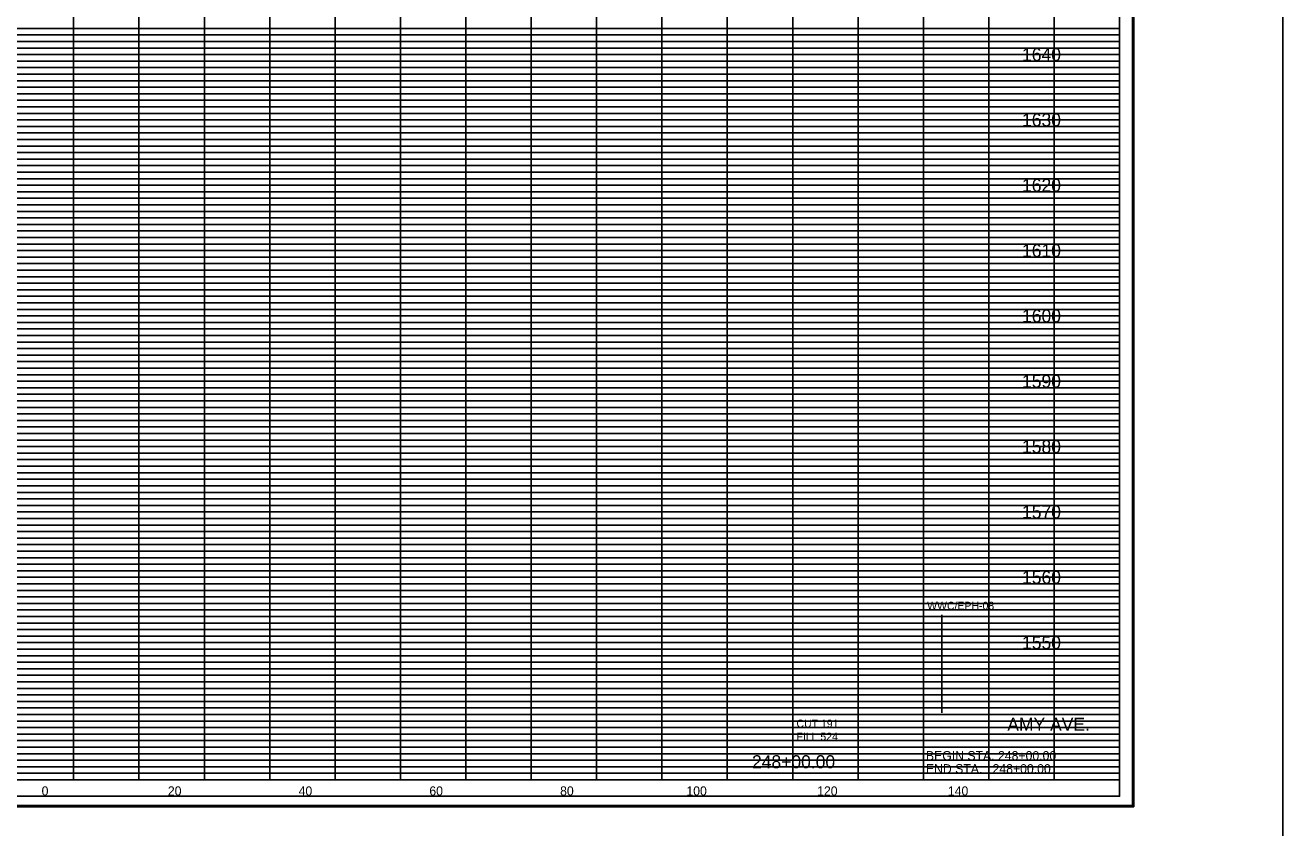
# Model space of a CAD drawing. Extents: x 955 to 1375, y 1248 to 3657.
# Drawn here: x 1152.6 to 1345, y 2612.7 to 2735.5 of the extents above; entities that cross this region are included whole.
import ezdxf

# ---------------------------------------------------------------- set-up
doc = ezdxf.new("R2010")
doc.units = 0
for name, color, linetype in [('DESIGN - SHEET - Corner Text', 7, 'Continuous'), ('DESIGN - SHEET - Light Grid', 7, 'Continuous'), ('DESIGN - SHEET - Linework', 7, 'Continuous'), ('DESIGN - SHEET - Plot Shape', 7, 'Continuous'), ('DESIGN - TYPICAL - Text', 7, 'Continuous'), ('DESIGN - UTILITIES - Cable (Overhead) with Text', 7, 'Continuous'), ('SURVEY - NON-TRANSPORTATION - Features', 7, 'Continuous'), ('SURVEY - NON-TRANSPORTATION - Features Text', 7, 'Continuous')]:
    doc.layers.add(name, color=color, linetype=linetype)

# ---------------------------------------------------------------- blocks, each defined once
blk = doc.blocks.new('XSTSHT')
at = {"layer": 'DESIGN - SHEET - Light Grid'}
for p, q in [((8, 11.5), (16, 11.5)), ((8, 11.4), (16, 11.4)), ((16, 11.5), (24, 11.5)), ((16, 11.4), (24, 11.4)), ((24, 11.5), (32, 11.5)), ((24, 11.4), (32, 11.4)), ((8, 11.3), (16, 11.3)), ((8, 11.2), (16, 11.2)), ((16, 11.3), (24, 11.3)), ((16, 11.2), (24, 11.2)), ((24, 11.3), (32, 11.3)), ((24, 11.2), (32, 11.2)), ((8, 11.1), (16, 11.1)), ((16, 11.1), (24, 11.1)), ((24, 11.1), (32, 11.1)), ((8, 10.9), (16, 10.9)), ((8, 10.8), (16, 10.8)), ((16, 10.9), (24, 10.9)), ((16, 10.8), (24, 10.8)), ((24, 10.9), (32, 10.9)), ((24, 10.8), (32, 10.8)), ((8, 10.7), (16, 10.7)), ((8, 10.6), (16, 10.6)), ((16, 10.7), (24, 10.7)), ((16, 10.6), (24, 10.6)), ((24, 10.7), (32, 10.7)), ((24, 10.6), (32, 10.6)), ((8, 10.5), (16, 10.5)), ((8, 10.4), (16, 10.4)), ((16, 10.5), (24, 10.5)), ((16, 10.4), (24, 10.4)), ((24, 10.5), (32, 10.5)), ((24, 10.4), (32, 10.4)), ((8, 10.3), (16, 10.3)), ((8, 10.2), (16, 10.2)), ((16, 10.3), (24, 10.3)), ((16, 10.2), (24, 10.2)), ((24, 10.3), (32, 10.3)), ((24, 10.2), (32, 10.2)), ((8, 10.1), (16, 10.1)), ((16, 10.1), (24, 10.1)), ((24, 10.1), (32, 10.1)), ((8, 9.9), (16, 9.9)), ((16, 9.9), (24, 9.9)), ((24, 9.9), (32, 9.9)), ((8, 9.8), (16, 9.8)), ((8, 9.7), (16, 9.7)), ((16, 9.8), (24, 9.8)), ((16, 9.7), (24, 9.7)), ((24, 9.8), (32, 9.8)), ((24, 9.7), (32, 9.7)), ((8, 9.6), (16, 9.6)), ((8, 9.5), (16, 9.5)), ((16, 9.6), (24, 9.6)), ((16, 9.5), (24, 9.5)), ((24, 9.6), (32, 9.6)), ((24, 9.5), (32, 9.5)), ((8, 9.4), (16, 9.4)), ((8, 9.3), (16, 9.3)), ((16, 9.4), (24, 9.4)), ((16, 9.3), (24, 9.3)), ((24, 9.4), (32, 9.4)), ((24, 9.3), (32, 9.3)), ((8, 9.2), (16, 9.2)), ((8, 9.1), (16, 9.1)), ((16, 9.2), (24, 9.2)), ((16, 9.1), (24, 9.1)), ((24, 9.2), (32, 9.2)), ((24, 9.1), (32, 9.1)), ((8, 8.9), (16, 8.9)), ((16, 8.9), (24, 8.9)), ((24, 8.9), (32, 8.9)), ((8, 8.8), (16, 8.8)), ((8, 8.7), (16, 8.7)), ((16, 8.8), (24, 8.8)), ((16, 8.7), (24, 8.7)), ((24, 8.8), (32, 8.8)), ((24, 8.7), (32, 8.7)), ((8, 8.6), (16, 8.6)), ((8, 8.5), (16, 8.5)), ((16, 8.6), (24, 8.6)), ((16, 8.5), (24, 8.5)), ((24, 8.6), (32, 8.6)), ((24, 8.5), (32, 8.5)), ((8, 8.4), (16, 8.4)), ((8, 8.3), (16, 8.3)), ((16, 8.4), (24, 8.4)), ((16, 8.3), (24, 8.3)), ((24, 8.4), (32, 8.4)), ((24, 8.3), (32, 8.3)), ((8, 8.2), (16, 8.2)), ((8, 8.1), (16, 8.1)), ((16, 8.2), (24, 8.2)), ((16, 8.1), (24, 8.1)), ((24, 8.2), (32, 8.2)), ((24, 8.1), (32, 8.1)), ((8, 7.9), (16, 7.9)), ((16, 7.9), (24, 7.9)), ((24, 7.9), (32, 7.9)), ((8, 7.8), (16, 7.8)), ((8, 7.7), (16, 7.7)), ((16, 7.8), (24, 7.8)), ((16, 7.7), (24, 7.7)), ((24, 7.8), (32, 7.8)), ((24, 7.7), (32, 7.7)), ((8, 7.6), (16, 7.6)), ((16, 7.6), (24, 7.6)), ((24, 7.6), (32, 7.6)), ((8, 7.5), (16, 7.5)), ((8, 7.4), (16, 7.4)), ((16, 7.5), (24, 7.5)), ((16, 7.4), (24, 7.4)), ((24, 7.5), (32, 7.5)), ((24, 7.4), (32, 7.4)), ((8, 7.3), (16, 7.3)), ((8, 7.2), (16, 7.2)), ((16, 7.3), (24, 7.3)), ((16, 7.2), (24, 7.2)), ((24, 7.3), (32, 7.3)), ((24, 7.2), (32, 7.2)), ((8, 7.1), (16, 7.1)), ((16, 7.1), (24, 7.1)), ((24, 7.1), (32, 7.1)), ((8, 6.9), (16, 6.9)), ((8, 6.8), (16, 6.8)), ((16, 6.9), (24, 6.9)), ((16, 6.8), (24, 6.8)), ((24, 6.9), (32, 6.9)), ((24, 6.8), (32, 6.8)), ((8, 6.7), (16, 6.7)), ((8, 6.6), (16, 6.6)), ((16, 6.7), (24, 6.7)), ((16, 6.6), (24, 6.6)), ((24, 6.7), (32, 6.7)), ((24, 6.6), (32, 6.6)), ((8, 6.5), (16, 6.5)), ((8, 6.4), (16, 6.4)), ((16, 6.5), (24, 6.5)), ((16, 6.4), (24, 6.4)), ((24, 6.5), (32, 6.5)), ((24, 6.4), (32, 6.4)), ((8, 6.3), (16, 6.3)), ((8, 6.2), (16, 6.2)), ((16, 6.3), (24, 6.3)), ((16, 6.2), (24, 6.2)), ((24, 6.3), (32, 6.3)), ((24, 6.2), (32, 6.2)), ((8, 6.1), (16, 6.1)), ((16, 6.1), (24, 6.1)), ((24, 6.1), (32, 6.1)), ((8, 5.9), (16, 5.9)), ((8, 5.8), (16, 5.8)), ((16, 5.9), (24, 5.9)), ((16, 5.8), (24, 5.8)), ((24, 5.9), (32, 5.9)), ((24, 5.8), (32, 5.8)), ((8, 5.7), (16, 5.7)), ((8, 5.6), (16, 5.6)), ((16, 5.7), (24, 5.7)), ((16, 5.6), (24, 5.6)), ((24, 5.7), (32, 5.7)), ((24, 5.6), (32, 5.6)), ((8, 5.5), (16, 5.5)), ((8, 5.4), (16, 5.4)), ((16, 5.5), (24, 5.5)), ((16, 5.4), (24, 5.4)), ((24, 5.5), (32, 5.5)), ((24, 5.4), (32, 5.4)), ((8, 5.3), (16, 5.3)), ((8, 5.2), (16, 5.2)), ((16, 5.3), (24, 5.3)), ((16, 5.2), (24, 5.2)), ((24, 5.3), (32, 5.3)), ((24, 5.2), (32, 5.2)), ((8, 5.1), (16, 5.1)), ((16, 5.1), (24, 5.1)), ((24, 5.1), (32, 5.1)), ((8, 4.9), (16, 4.9)), ((16, 4.9), (24, 4.9)), ((24, 4.9), (32, 4.9)), ((8, 4.8), (16, 4.8)), ((8, 4.7), (16, 4.7)), ((16, 4.8), (24, 4.8)), ((16, 4.7), (24, 4.7)), ((24, 4.8), (32, 4.8)), ((24, 4.7), (32, 4.7)), ((8, 4.6), (16, 4.6)), ((8, 4.5), (16, 4.5)), ((16, 4.6), (24, 4.6)), ((16, 4.5), (24, 4.5)), ((24, 4.6), (32, 4.6)), ((24, 4.5), (32, 4.5)), ((8, 4.4), (16, 4.4)), ((8, 4.3), (16, 4.3)), ((16, 4.4), (24, 4.4)), ((16, 4.3), (24, 4.3)), ((24, 4.4), (32, 4.4)), ((24, 4.3), (32, 4.3)), ((8, 4.2), (16, 4.2)), ((8, 4.1), (16, 4.1)), ((16, 4.2), (24, 4.2)), ((16, 4.1), (24, 4.1)), ((24, 4.2), (32, 4.2)), ((24, 4.1), (32, 4.1)), ((8, 3.9), (16, 3.9)), ((16, 3.9), (24, 3.9)), ((24, 3.9), (32, 3.9)), ((8, 3.8), (16, 3.8)), ((8, 3.7), (16, 3.7)), ((16, 3.8), (24, 3.8)), ((16, 3.7), (24, 3.7)), ((24, 3.8), (32, 3.8)), ((24, 3.7), (32, 3.7)), ((8, 3.6), (16, 3.6)), ((8, 3.5), (16, 3.5)), ((16, 3.6), (24, 3.6)), ((16, 3.5), (24, 3.5)), ((24, 3.6), (32, 3.6)), ((24, 3.5), (32, 3.5)), ((8, 3.4), (16, 3.4)), ((8, 3.3), (16, 3.3)), ((16, 3.4), (24, 3.4)), ((16, 3.3), (24, 3.3)), ((24, 3.4), (32, 3.4)), ((24, 3.3), (32, 3.3)), ((8, 3.2), (16, 3.2)), ((8, 3.1), (16, 3.1)), ((16, 3.2), (24, 3.2)), ((16, 3.1), (24, 3.1)), ((24, 3.2), (32, 3.2)), ((24, 3.1), (32, 3.1)), ((8, 2.9), (16, 2.9)), ((16, 2.9), (24, 2.9)), ((24, 2.9), (32, 2.9)), ((8, 2.8), (16, 2.8)), ((8, 2.7), (16, 2.7)), ((16, 2.8), (24, 2.8)), ((16, 2.7), (24, 2.7)), ((24, 2.8), (32, 2.8)), ((24, 2.7), (32, 2.7)), ((8, 2.6), (16, 2.6)), ((16, 2.6), (24, 2.6)), ((24, 2.6), (32, 2.6)), ((8, 2.5), (16, 2.5)), ((8, 2.4), (16, 2.4)), ((16, 2.5), (24, 2.5)), ((16, 2.4), (24, 2.4)), ((24, 2.5), (32, 2.5)), ((24, 2.4), (32, 2.4)), ((8, 2.3), (16, 2.3)), ((8, 2.2), (16, 2.2)), ((16, 2.3), (24, 2.3)), ((16, 2.2), (24, 2.2)), ((24, 2.3), (32, 2.3)), ((24, 2.2), (32, 2.2)), ((8, 2.1), (16, 2.1)), ((16, 2.1), (24, 2.1)), ((24, 2.1), (32, 2.1)), ((8, 1.9), (16, 1.9)), ((8, 1.8), (16, 1.8)), ((16, 1.9), (24, 1.9)), ((16, 1.8), (24, 1.8)), ((24, 1.9), (32, 1.9)), ((24, 1.8), (32, 1.8)), ((8, 1.7), (16, 1.7)), ((8, 1.6), (16, 1.6)), ((16, 1.7), (24, 1.7)), ((16, 1.6), (24, 1.6)), ((24, 1.7), (32, 1.7)), ((24, 1.6), (32, 1.6)), ((8, 1.5), (16, 1.5)), ((8, 1.4), (16, 1.4)), ((16, 1.5), (24, 1.5)), ((16, 1.4), (24, 1.4)), ((24, 1.5), (32, 1.5)), ((24, 1.4), (32, 1.4)), ((8, 1.3), (16, 1.3)), ((8, 1.2), (16, 1.2)), ((16, 1.3), (24, 1.3)), ((16, 1.2), (24, 1.2)), ((24, 1.3), (32, 1.3)), ((24, 1.2), (32, 1.2)), ((8, 1.1), (16, 1.1)), ((16, 1.1), (24, 1.1)), ((24, 1.1), (32, 1.1)), ((8, 0.9), (16, 0.9)), ((8, 0.8), (16, 0.8)), ((16, 0.9), (24, 0.9)), ((16, 0.8), (24, 0.8)), ((24, 0.9), (32, 0.9)), ((24, 0.8), (32, 0.8)), ((8, 0.7), (16, 0.7)), ((8, 0.6), (16, 0.6)), ((16, 0.7), (24, 0.7)), ((16, 0.6), (24, 0.6)), ((24, 0.7), (32, 0.7)), ((24, 0.6), (32, 0.6)), ((8, 0.5), (16, 0.5)), ((8, 0.4), (16, 0.4)), ((16, 0.5), (24, 0.5)), ((16, 0.4), (24, 0.4)), ((24, 0.5), (32, 0.5)), ((24, 0.4), (32, 0.4)), ((8, 0.3), (16, 0.3)), ((8, 0.2), (16, 0.2)), ((16, 0.3), (24, 0.3)), ((16, 0.2), (24, 0.2)), ((24, 0.3), (32, 0.3)), ((24, 0.2), (32, 0.2)), ((8, 0.1), (16, 0.1)), ((16, 0.1), (24, 0.1)), ((24, 0.1), (32, 0.1))]:
    blk.add_line(p, q, dxfattribs=at)
at = {"layer": 'DESIGN - SHEET - Linework'}
for p, q in [((32.217, 21.414), (32.217, -0.414)), ((16, 0), (16, 21)), ((17, 0), (17, 21)), ((18, 0), (18, 21)), ((19, 0), (19, 21)), ((20, 0), (20, 21)), ((21, 0), (21, 21)), ((22, 0), (22, 21)), ((23, 0), (23, 21)), ((24, 0), (24, 21)), ((25, 0), (25, 21)), ((26, 0), (26, 21)), ((27, 0), (27, 21)), ((28, 0), (28, 20)), ((29, 0), (29, 20)), ((30, 0), (30, 20)), ((31, 0), (31, 20)), ((0, 11), (32, 11)), ((0, 10), (32, 10)), ((0, 9), (32, 9)), ((0, 8), (32, 8)), ((0, 7), (32, 7)), ((0, 6), (32, 6)), ((0, 5), (32, 5)), ((0, 4), (32, 4)), ((0, 3), (32, 3)), ((0, 2), (32, 2)), ((0, 1), (32, 1)), ((-1.823, -0.414), (32.217, -0.414))]:
    blk.add_line(p, q, dxfattribs=at)
blk.add_lwpolyline([(0, 21), (0, 0), (32, 0), (32, 21), (0, 21)], dxfattribs=at)
at = {"layer": 'DESIGN - SHEET - Plot Shape'}
for points in [[(-1.803, 21.394), (32.197, 21.394), (32.197, -0.394), (-1.803, -0.394)], [(-0.85, 21), (32, 21), (32, -0.25), (-0.85, -0.25)]]:
    blk.add_lwpolyline(points, close=True, dxfattribs=at)

msp = doc.modelspace()

# ---------------------------------------------------------------- linework, layer by layer
at = {"layer": 'DESIGN - SHEET - Plot Shape'}
msp.add_lwpolyline([(991.5, 2617.5), (1320, 2617.5), (1320, 2830), (991.5, 2830)], close=True, dxfattribs=at)
at = {"layer": 'SURVEY - NON-TRANSPORTATION - Features'}
msp.add_line((1292.81, 2630.23), (1292.81, 2645.23), dxfattribs=at)
at = {"layer": 'SURVEY - NON-TRANSPORTATION - Features Text'}
msp.add_lwpolyline([(955.41, 1505.76), (1344.98, 1505.76), (1344.98, 3398.01), (955.41, 3398.01)], close=True, dxfattribs=at)

# ---------------------------------------------------------------- block references
at = {"layer": 'DESIGN - UTILITIES - Cable (Overhead) with Text', "xscale": 10, "yscale": 10}
msp.add_blockref('XSTSHT', (1000, 2620), dxfattribs=at)

# ---------------------------------------------------------------- texts
at = {"layer": 'DESIGN - SHEET - Corner Text'}
for s, height, p in [('AMY AVE.', 2, (1302.83, 2627.5)), ('BEGIN STA. 248+00.00', 1.4, (1290.38, 2623)), ('END STA.   248+00.00', 1.4, (1290.38, 2621))]:
    msp.add_text(s, height=height, dxfattribs=at).set_placement(p)
at = {"layer": 'DESIGN - TYPICAL - Text'}
for s, height, p in [('     1640     ', 2, (1301.37, 2730)), ('     1630     ', 2, (1301.37, 2720)), ('     1620     ', 2, (1301.37, 2710)), ('     1610     ', 2, (1301.37, 2700)), ('     1600     ', 2, (1301.37, 2690)), ('     1590     ', 2, (1301.37, 2680)), ('     1580     ', 2, (1301.37, 2670)), ('     1570     ', 2, (1301.37, 2660)), ('     1560     ', 2, (1301.37, 2650)), ('     1550     ', 2, (1301.37, 2640)), ('CUT 191', 1.2, (1270.58, 2628.02)), ('FILL 524', 1.2, (1270.58, 2626.02)), ('     248+00.00     ', 2, (1260.06, 2621.77)), ('     0     ', 1.4, (1152.51, 2617.6)), ('     0     ', 1.4, (1152.51, 2617.6)), ('     20     ', 1.4, (1171.82, 2617.6)), ('     40     ', 1.4, (1191.82, 2617.6)), ('     60     ', 1.4, (1211.82, 2617.6)), ('     80     ', 1.4, (1231.82, 2617.6)), ('     100     ', 1.4, (1251.14, 2617.6)), ('     120     ', 1.4, (1271.14, 2617.6)), ('     140     ', 1.4, (1291.14, 2617.6))]:
    msp.add_text(s, height=height, dxfattribs=at).set_placement(p)
at = {"layer": 'SURVEY - NON-TRANSPORTATION - Features'}
msp.add_text('WWC/EPH-08', height=1.2, dxfattribs=at).set_placement((1290.57, 2646.05))

doc.saveas('drawing.dxf')
